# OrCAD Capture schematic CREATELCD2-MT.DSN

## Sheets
1 P1: Title block: title: K4 LCD bridge; rev: 3.0; note: Kinoma Create
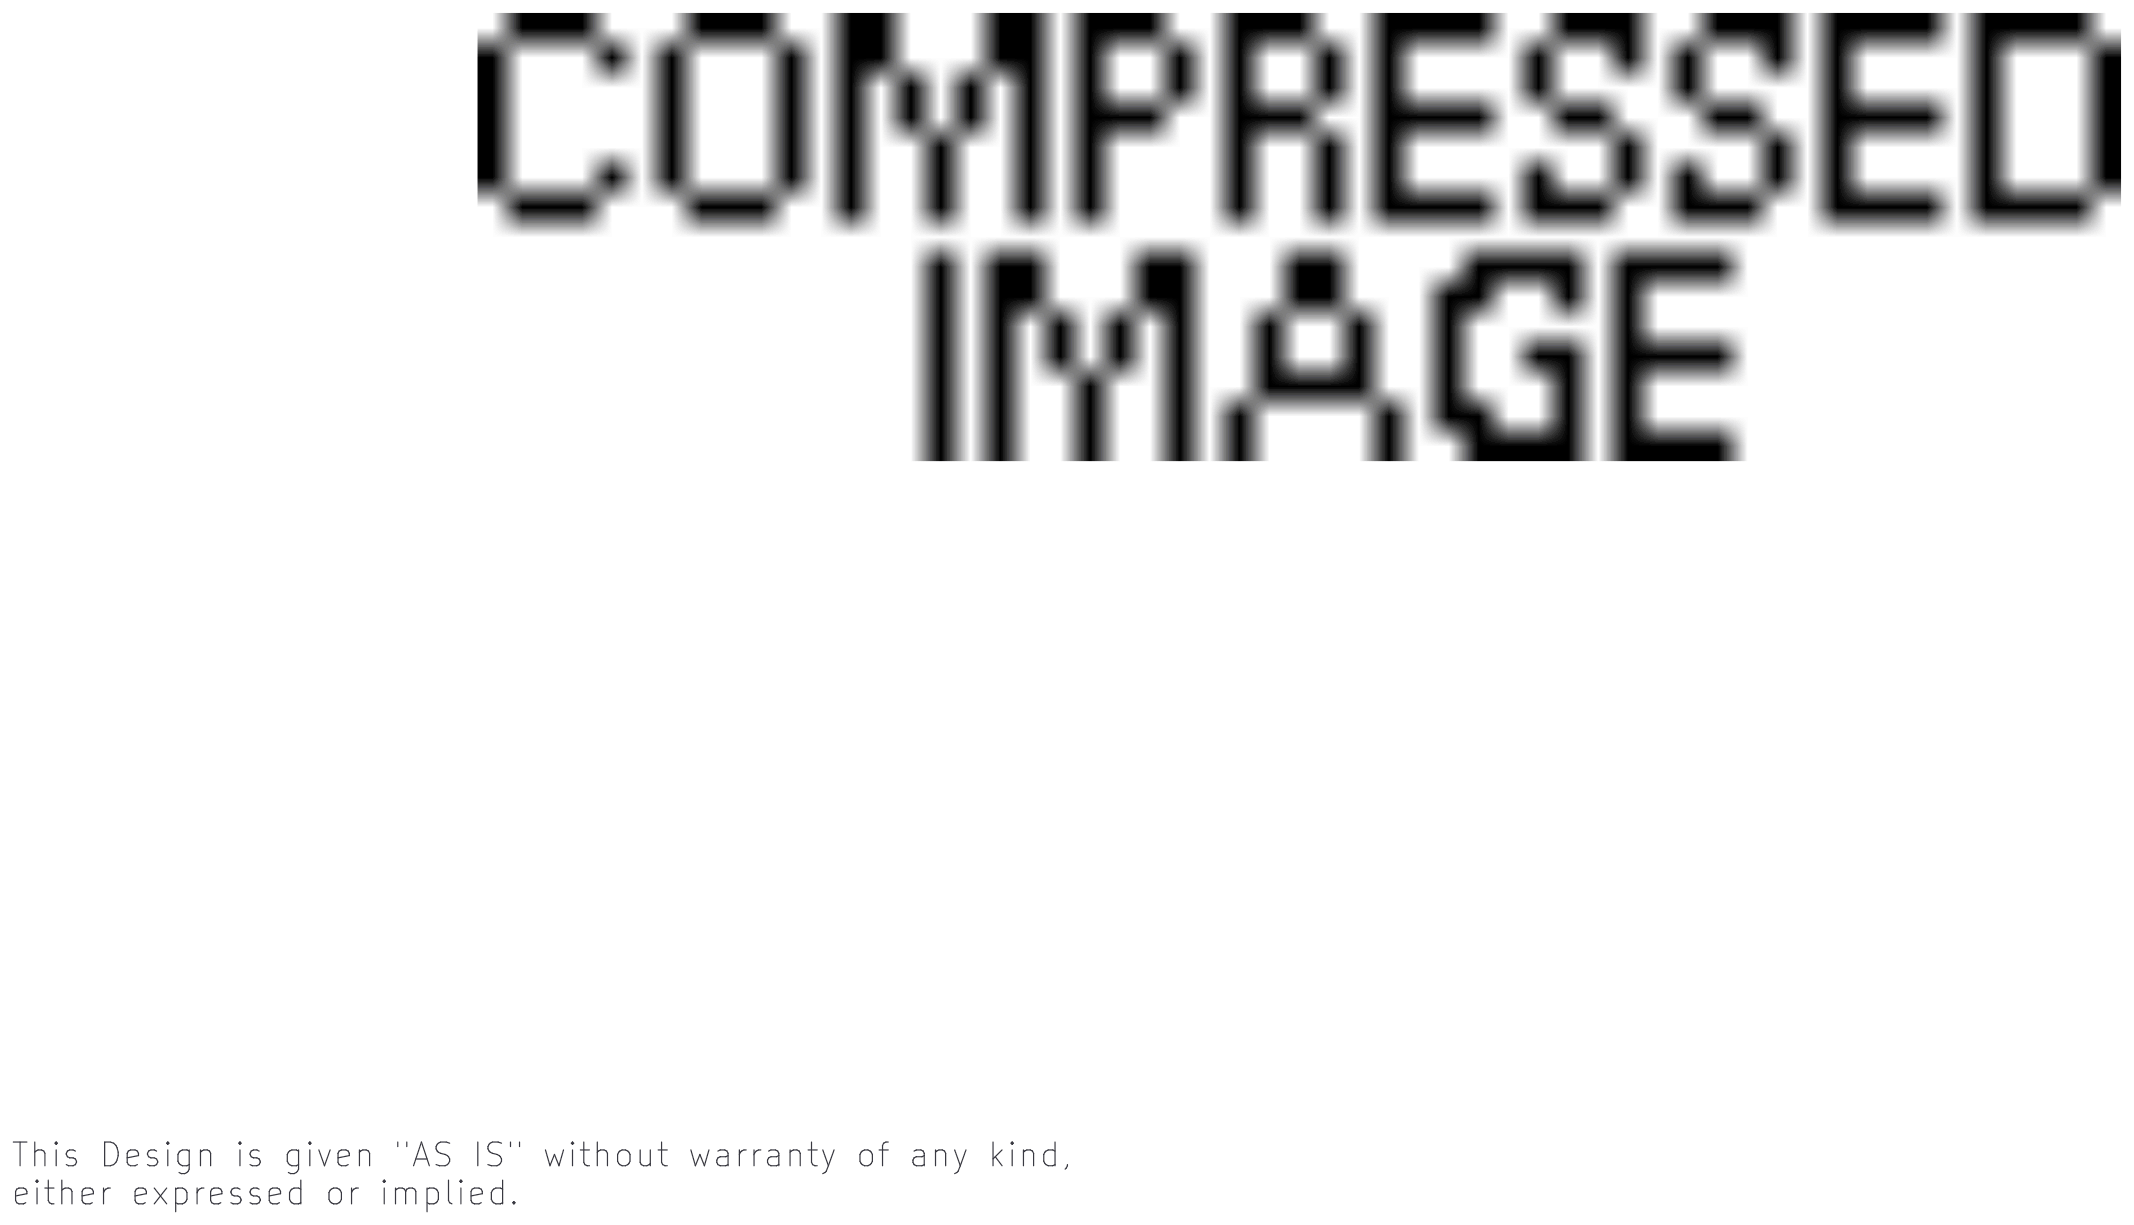
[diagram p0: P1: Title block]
2 P2: Microtech 320x240 3.5": size Custom; title: LCD touch and battery; rev: 1.0
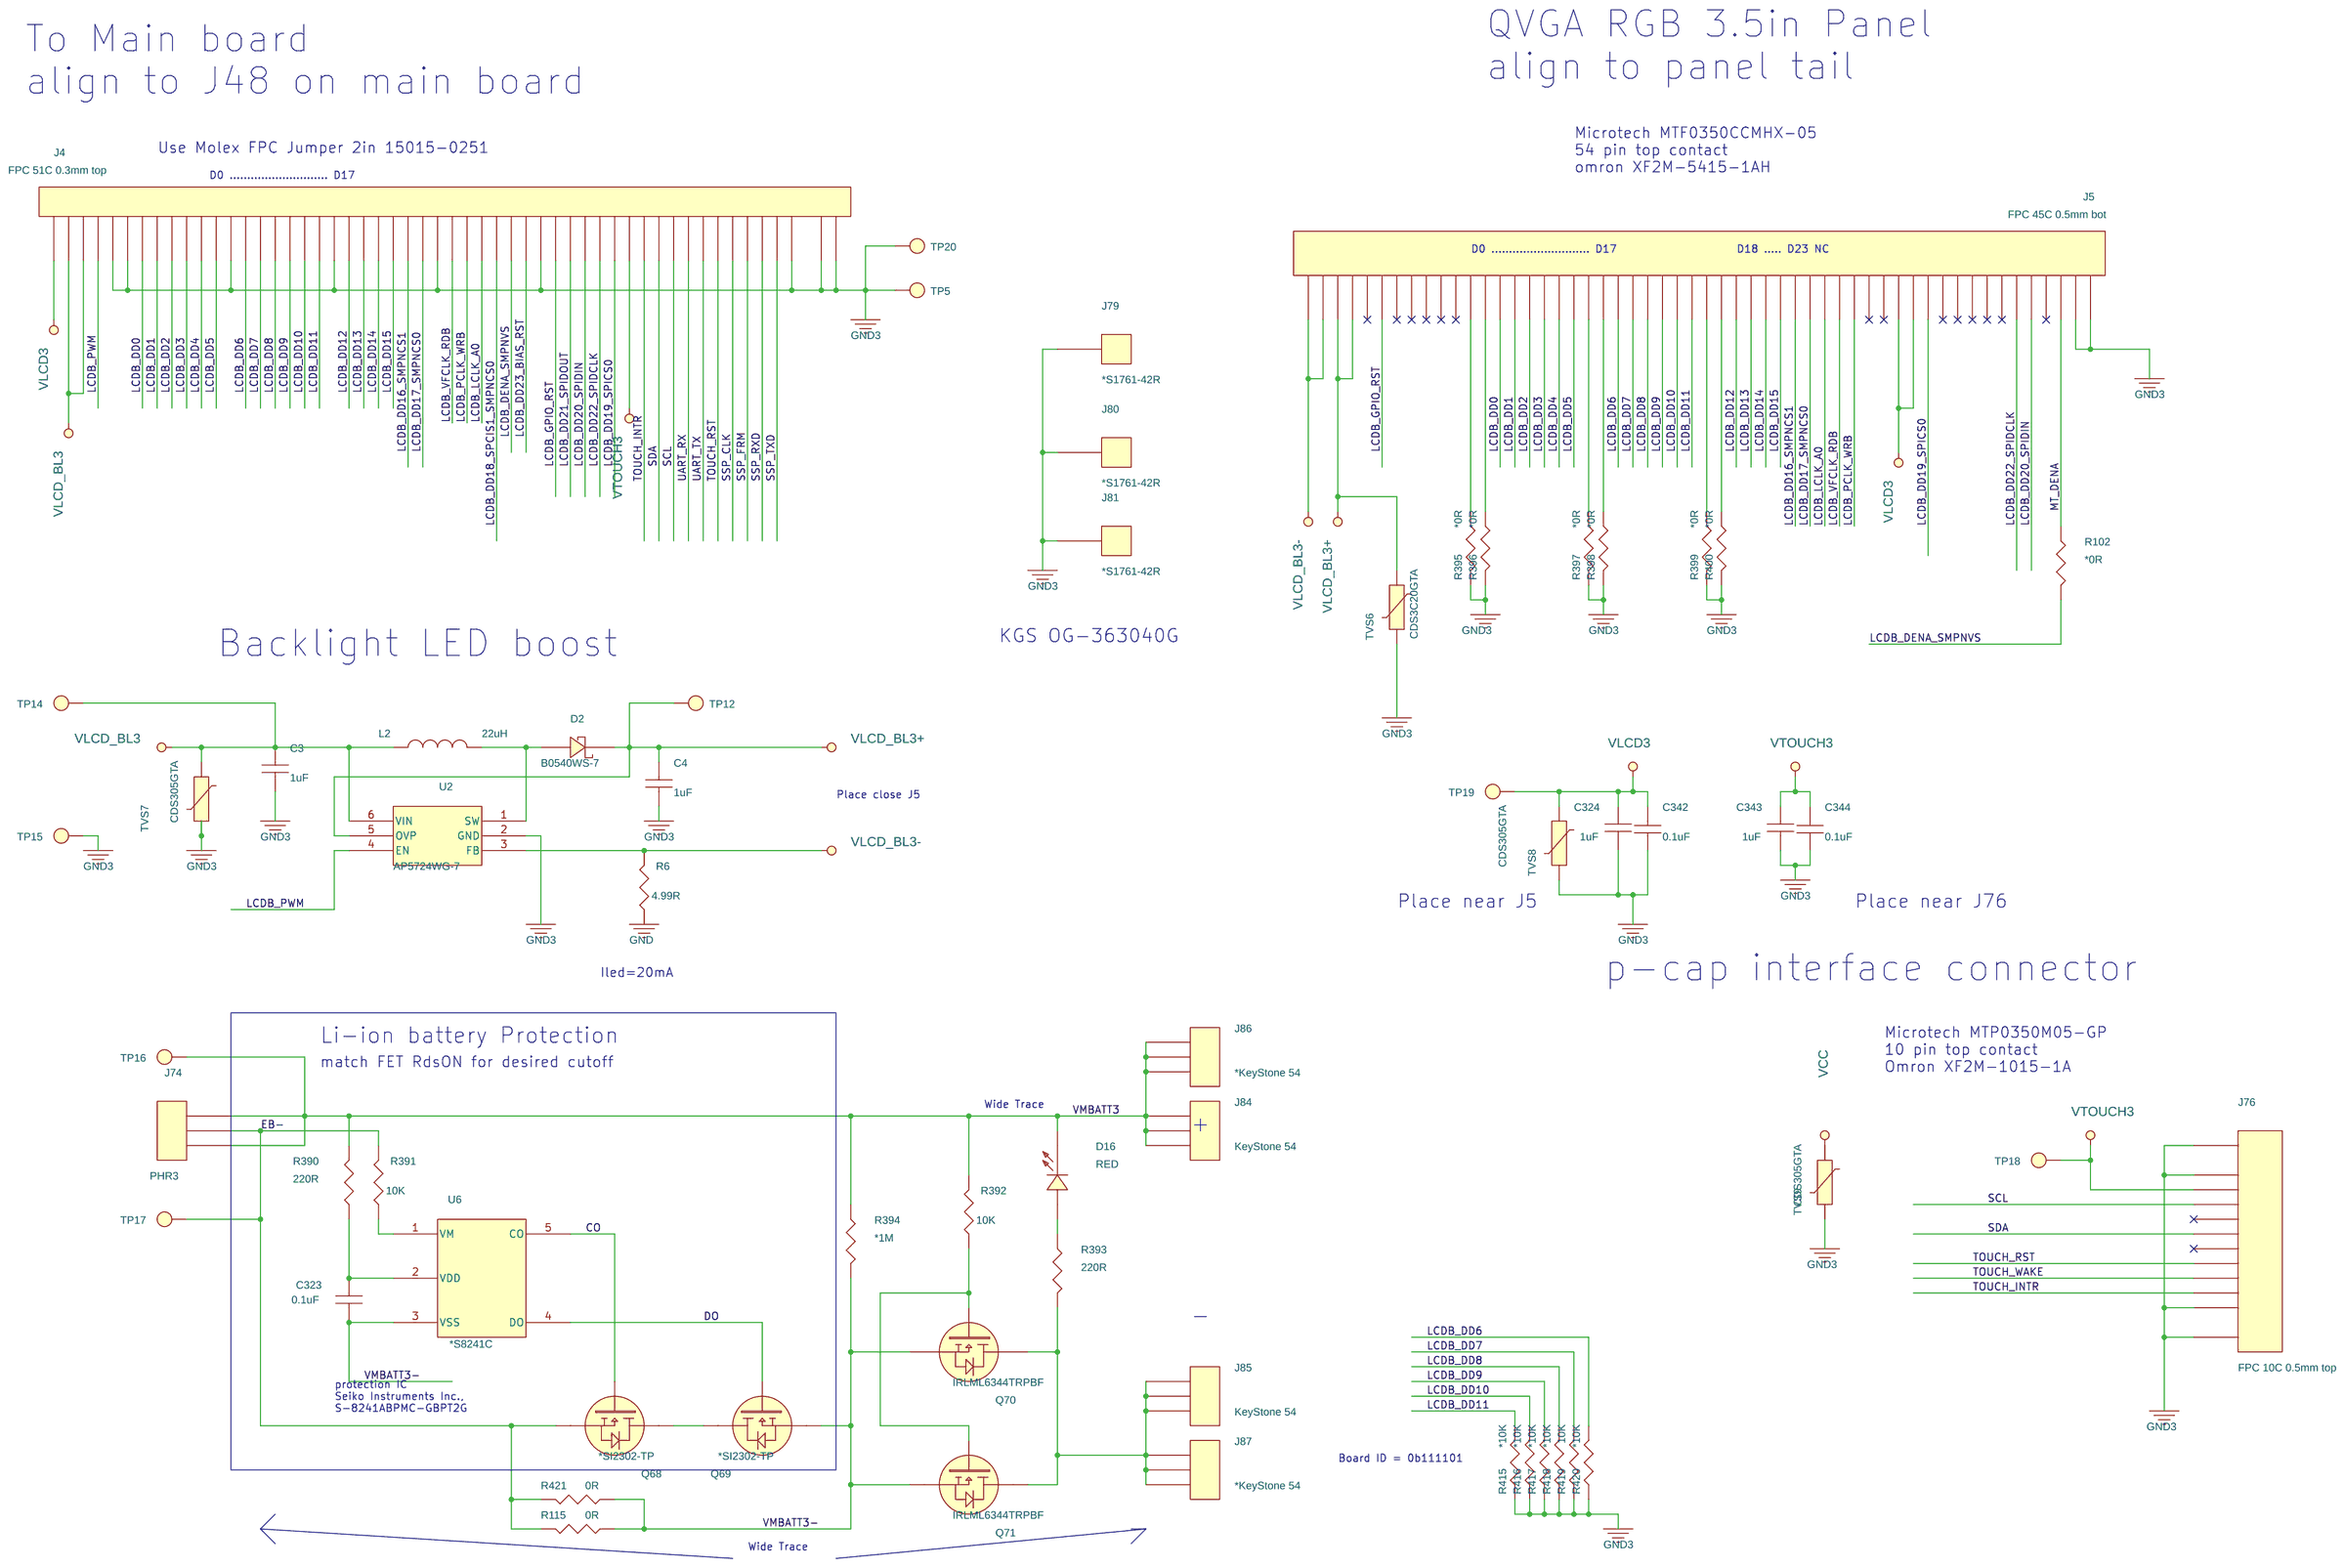
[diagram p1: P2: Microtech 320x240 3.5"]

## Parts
C3  1uF  [C0603]
C4  1uF  [C0603]
C323  0.1uF  [C-0402]
C324  1uF  [C0603]
C342  0.1uF  [C-0402]
C343  1uF  [C0603]
C344  0.1uF  [C-0402]
D2  B0540WS-7  [SOD-323]
D16  RED  [LED0603]
J4  FPC 51C 0.3mm top  [FH35_51_0_3MM]
J5  FPC 45C 0.5mm bot  [XF2M-5415-1AH]
J74  PHR3  [JST_PHR3P_2mm]
J76  FPC 10C 0.5mm top  [XF2M-1015-1A]
J79  *S1761-42R  [S1761-42R]
J80  *S1761-42R  [S1761-42R]
J81  *S1761-42R  [S1761-42R]
J84  KeyStone 54  [KSTONE54TH]
J85  KeyStone 54  [KSTONE54TH]
J86  *KeyStone 54  [KSTONE54TH]
J87  *KeyStone 54  [KSTONE54TH]
L2  22uH  [L-NR4012]
Q68  *SI2302-TP  [SOT-23a]
Q69  *SI2302-TP  [SOT-23a]
Q70  IRLML6344TRPBF  [SOT-23a]
Q71  IRLML6344TRPBF  [SOT-23a]
R6  4.99R  [R-0402]
R102  *0R  [R-0402]
R115  0R  [R-0603]
R390  220R  [R0402]
R391  10K  [R0402]
R392  10K  [R0402]
R393  220R  [R0402]
R394  *1M  [R0402]
R395  *0R  [R-0402]
R396  *0R  [R-0402]
R397  *0R  [R-0402]
R398  *0R  [R-0402]
R399  *0R  [R-0402]
R400  *0R  [R-0402]
R415  *10K  [R0402]
R416  *10K  [R0402]
R417  *10K  [R0402]
R418  *10K  [R0402]
R419  10K  [R0402]
R420  *10K  [R0402]
R421  0R  [R-0603]
TP5  *T_POINT  [TP]
TP12  *T_POINT  [TP040]
TP14  *T_POINT  [TP040]
TP15  *T_POINT  [TP040]
TP16  *T_POINT  [TP040]
TP17  *T_POINT  [TP040]
TP18  *T_POINT  [TP040]
TP19  *T_POINT  [TP040]
TP20  *T_POINT  [TP]
TVS6  CDS3C20GTA  [D0603]
TVS7  CDS305GTA  [D0603]
TVS8  CDS305GTA  [D0603]
TVS9  CDS305GTA  [D0603]
U2  AP5724WG-7  [SOT-23-6]
U6  *S8241C  [sot23-5]

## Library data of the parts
C3 C4 C324 C343 = CAP_NP: Desc: CAP CER 1UF 25V 10% X5R 0603; OPTION: TM035; Part Num: TMK107BJ105KA-T; Vendor: Taiyo
C323 = CAP_NP: CAP CER .10UF 10V X5R 10% 0402; Desc: CAP CER .10UF 10V X7R 0402; Distributor: Digi-Key; Distributor Part Number: 445-1265-1-ND; Manufacturer: C1005X5R1A104K; Manufacturer Part Number: CAP CER .10UF 10V X5R 10% 0402; Part Num: C1005X7R1A104K; Vendor: TDK
C342 C344 = CAPACITOR_NON-POL: Desc: CAP CER .10UF 10V X7R 0402; OPTION: DBG; Part Num: C1005X7R1A104K; Vendor: TDK
D2 = DIODE_SCHOTTKY21: DIODE SCHOTTKY 1A 40V SMA; Desc: DIODE SCHOTTKY 40V 0.5A SOD323; Manufacturer: Diodes Inc; OPTION: TM035; Vendor: Diodes
D16 = LED_SINGLE: Desc: LED RED RECT CLEAR 0603; Part Num: LTST-C193KRKT-5A; Vendor: Lite-On
J4 = CONN_FLEX_51: Desc: CONN FPC 51POS 0.30MM R/A; OPTION: TM035; Part Num: 5025985193; Vendor: Molex
J5 = CONN_FLEX_54: Desc: CONN FPC ONE-TOUCH LCK .5MM 54; OPTION: TM035; Vendor: Omron
J74 = CON3: Desc: CONN HEADER PH SIDE 3POS 2MM SMD; Part Num: S3B-PH-SM4-TB(LF)(SN); Vendor: JST
J76 = FPC10-2mtg: Desc: CONN FPC/FFC 10POS .5MM R/A SMD; Distributor: Digi-Key; Distributor PN: 609-4306-2-ND; Manufacturer: FCI; Manufacturer PN: SFV10R-2STE1HLF; Vendor: Omron
J79 = CON1: Desc: RFI SHIELD FINGER GOLD 3.5MM SMD; Vendor: Harwin
J80 J81 = CON1: Desc: RFI SHIELD FINGER GOLD 3.5MM SMD
J84-J87 = CON3: Part Num: 54; Vendor: Keystone; desc: BATTERY CLIP 18MM 18650 CELL
L2 = INDUCTOR: Desc: INDUCTOR 22UH 20% SMD; OPTION: TM035; Part Num: NR4012T220M; Vendor: Taiyo
Q68 Q69 = NMOS3: Desc: MOSFET N-CH 20V 3A SOT-23; Part Num: SI2302-TP; Vendor: MCC
Q70 Q71 = NMOS3: Desc: MOSFET N-CH 30V 5A SOT23; Vendor: IRF
R6 = Res_0: Desc: RES 4.99 OHM 1/16W 1% 0402 SMD; OPTION: TM035; Part Num: CRCW04024R99FKED; Vendor: Vishay
R102 = Res_0: Desc: RES 0.0 OHM 1/10W 0402 SMD; Mfr: Generic; OPTION: LIPO; Part Num: ERJ-2GE0R00X; Vendor: Panasonic; ccc: RES 0.0 OHM 1/10W 0402 SMD
R115 R421 = R_0: Desc: RES 0.0 OHM 1/10W 0603 SMD; Mfr: Generic; Part Num: ERJ-3GEY0R00V; Vendor: Panasonic
R390 R393 = Res_0: Desc: RES 220 OHM 1/10W 1% 0402 SMD; Part Num: ERJ-2RKF2200X; Vendor: Panasonic
R391 R392 R415-R420 = Res_0: Desc: RES 10K OHM 1/10W 5% 0402 SMD; Part Num: ERJ-2GEJ103X; Vendor: Panasonic
R394 = Res_0: Desc: RES 1M OHM 1/10W 5% 0402 SMD; Part Num: ERJ-2GEJ105X; Vendor: Panasonic
R395-R400 = Res_0: Desc: RES 0.0 OHM 1/10W 0402 SMD; Distributor: Digi-Key; Distributor PN: P15979CT-ND; Manufacturer: Panasonic Electronic Components; Manufacturer PN: ERJ-1GN0R00C; Mfr: Generic; OPTION: LIPO; Part Num: ERJ-2GE0R00X; Vendor: Panasonic; ccc: RES 0.0 OHM 1/10W 0402 SMD
TP5 TP20 = T_POINT: Desc: SMT Test Point; OPTION: TM035; Part Num: NA; Vendor: Test
TP12 TP14-TP19 = T_POINT: Desc: SMT Test Point; Part Num: NA; Vendor: Test
TVS6 = MOV-small: Desc: VARISTOR 25V 30A 0603; Part Num: B72500D200A60V9; Vendor: Epcos
TVS7-TVS9 = MOV-small: Desc: VARISTOR 6.4V 30A 0603; Part Num: B72500D50A60; Vendor: Epcos
U2 = AP5724WG-7: Desc: IC LED DRVR WHITE BCKLGT SOT23-6; OPTION: TM035; Vendor: Diodes
U6 = S8211C: Desc: IC BATT PROTECTION 1CELL SOT23-5; Part Num: S-8241ABPMC-GBPT2G

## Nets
GND3: C3.2 C4.2 C324.2 C342.1 C343.2 C344.1 J4.5 J4.6 J4.13 J4.20 J4.27 J4.34 J4.51 J4.M1 J4.M2 J5.53 J5.54 J76.1 J76.10 J76.M1 J76.M2 J79.1 J80.1 J81.1 R6.2 R395.1 R396.1 R397.1 R398.1 R399.1 R400.1 R415.2 R416.2 R417.2 R418.2 R419.2 R420.2 TP5.1(TP) TP15.1(TP) TP20.1(TP) TVS6.1 TVS7.1 TVS8.1 TVS9.1 U2.2(GND)
CO: Q68.G U6.5(CO)
DO: Q69.G U6.4(DO)
EB-: J74.2 Q68.S R115.1 R391.1 R421.1 TP17.1(TP)
LCDB_DD0: J4.7 J5.14
LCDB_DD1: J4.8 J5.15
LCDB_DD2: J4.9 J5.16
LCDB_DD3: J4.10 J5.17
LCDB_DD4: J4.11 J5.18
LCDB_DD5: J4.12 J5.19
LCDB_DD6: J4.14 J5.22 R420.1
LCDB_DD7: J4.15 J5.23 R419.1
LCDB_DD8: J4.16 J5.24 R418.1
LCDB_DD9: J4.17 J5.25 R417.1
LCDB_DD10: J4.18 J5.26 R416.1
LCDB_DD11: J4.19 J5.27 R415.1
LCDB_DD12: J4.21 J5.30
LCDB_DD13: J4.22 J5.31
LCDB_DD14: J4.23 J5.32
LCDB_DD15: J4.24 J5.33
LCDB_DD16_SMPNCS1: J4.25 J5.34
LCDB_DD17_SMPNCS0: J4.26 J5.35
LCDB_DD18_SPCIS1_SMPNCS0: J4.31
LCDB_DD19_SPICS0: J4.39 J5.43
LCDB_DD20_SPIDIN: J4.37 J5.50
LCDB_DD21_SPIDOUT: J4.36
LCDB_DD22_SPIDCLK: J4.38 J5.49
LCDB_DD23_BIAS_RST: J4.33
LCDB_DENA_SMPNVS: J4.32 R102.1
LCDB_GPIO_RST: J4.35 J5.6
LCDB_LCLK_A0: J4.30 J5.36
LCDB_PCLK_WRB: J4.29 J5.38
LCDB_PWM: J4.4 U2.4(EN)
LCDB_VFCLK_RDB: J4.28 J5.37
MT_DENA: J5.52 R102.2
SCL: J4.43 J76.3
SDA: J4.42 J76.5
SSP_CLK: J4.47
SSP_FRM: J4.48
SSP_RXD: J4.49
SSP_TXD: J4.50
TOUCH_INTR: J4.41 J76.9
TOUCH_RST: J4.46 J76.7
TOUCH_WAKE: J76.8
UART_RX: J4.44
UART_TX: J4.45
VLCD3: C324.1 C342.2 J4.1 J5.41 J5.42 TP19.1(TP) TVS8.2
VLCD_BL3: C3.1 J4.2 J4.3 L2.1 TP14.1(TP) TVS7.2 U2.6(VIN)
VLCD_BL3+: C4.1 D2.1(K) J5.3 J5.4 TP12.1(TP) TVS6.2 U2.5(OVP)
VLCD_BL3-: J5.1 J5.2 R6.1 U2.3(FB)
VMBATT3: D16.2(CATHODE) J74.1 J74.3 J84.1 J84.2 J84.3 J86.1 J86.2 J86.3 R390.2 R392.1 R394.2 TP16.1(TP)
VMBATT3-: C323.2 Q69.S Q70.S Q71.S R115.2 R394.1 R421.2 U6.3(VSS)
VTOUCH3: C343.1 C344.2 J4.40 J76.2 TP18.1(TP) TVS9.2
N111357: D2.2(A) L2.2 U2.1(SW)
N228967: C323.1 R390.1 U6.2(VDD)
N229053: R391.2 U6.1(VM)
N229081: Q68.D Q69.D
N229207: J85.1 J85.2 J85.3 J87.1 J87.2 J87.3 Q70.D Q71.D R393.1
N229239: Q70.G Q71.G R392.2
N229297: D16.1(ANODE) R393.2
N236506: J5.12 R395.2
N236510: J5.13 R396.2
N236627: J5.20 R397.2
N236631: J5.21 R398.2
N236761: J5.28 R399.2
N236765: J5.29 R400.2

Not connected (* = marked no-connect by the designer): J5 5* 7* 8* 9* 10* 11* 39* 40* 44* 45* 46* 47* 48* 51*; J76 4* 6*

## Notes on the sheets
sheet 1
- This Design is given "AS IS" without warranty of any kind,
  either expressed or implied.
sheet 2
- QVGA RGB 3.5in Panel
  align to panel tail
- To Main board
  align to J48 on main board
- Microtech MTF0350CCMHX-05
  54 pin top contact
  omron XF2M-5415-1AH
- Use Molex FPC Jumper 2in 15015-0251
- D0 ............................ D17
- D0 ............................ D17
- D18 ..... D23 NC
- Backlight LED boost
- KGS OG-363040G
- Place close J5
- Place near J5
- Place near J76
- p-cap interface connector
- Iled=20mA
- Li-ion battery Protection
- Microtech MTP0350M05-GP
  10 pin top contact
  Omron XF2M-1015-1A
- match FET RdsON for desired cutoff
- Wide Trace
- +
- -
- protection IC
  Seiko Instruments Inc.,
  S-8241ABPMC-GBPT2G
- Board ID = 0b111101
- Wide Trace
